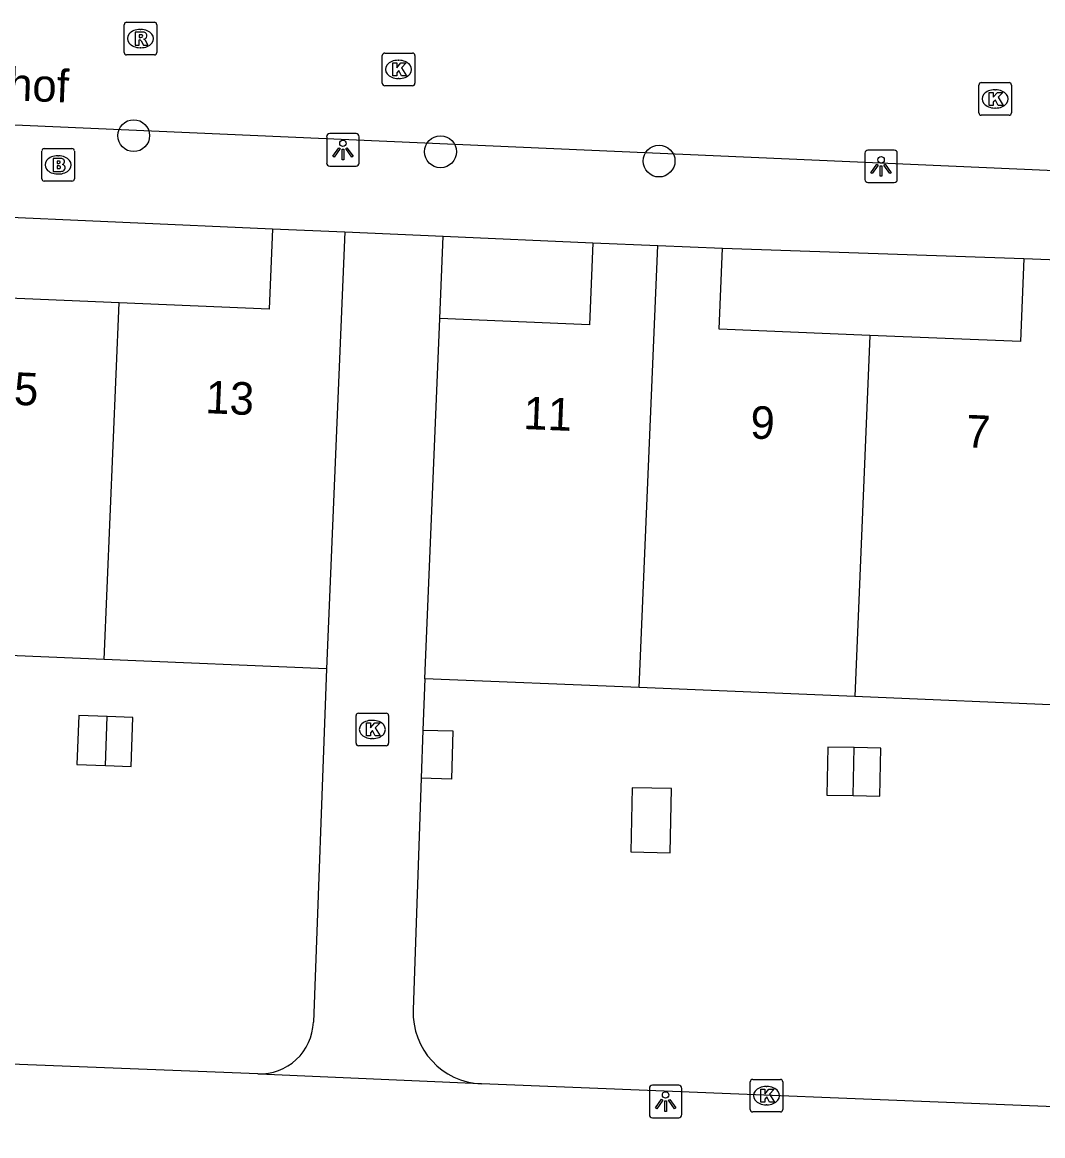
# Model space of a CAD drawing. Extents: x 160787 to 161428, y 386828 to 387483.
# Drawn here: x 161234.85 to 161266.19, y 386955.43 to 386989.61 of the extents above; entities that cross this region are included whole.
import ezdxf

# ---------------------------------------------------------------- set-up
doc = ezdxf.new("R2010")
doc.units = 0
for name, color, linetype in [('IMGEO_Boom', 7, 'Continuous'), ('IMGEO_Brandkraan', 7, 'Continuous'), ('IMGEO_Kolk', 7, 'Continuous'), ('IMGEO_Lichtpunt', 7, 'Continuous'), ('IMGEO_Openbare_ruimte_label', 7, 'Continuous'), ('IMGEO_Pand', 7, 'Continuous'), ('IMGEO_Pand_nummerreeks', 7, 'Continuous'), ('IMGEO_Parkeervlak_open', 7, 'Continuous'), ('IMGEO_Rijbaan_lokaal_open', 7, 'Continuous'), ('IMGEO_Rioolput', 7, 'Continuous'), ('IMGEO_Voetpad_open', 7, 'Continuous')]:
    doc.layers.add(name, color=color, linetype=linetype)

msp = doc.modelspace()

# ---------------------------------------------------------------- linework, layer by layer
at = {"layer": 'IMGEO_Boom'}
for centre in [(161238.273, 386986.13), (161247.693, 386985.636), (161254.405, 386985.35)]:
    msp.add_circle(centre, 0.489, dxfattribs=at)
at = {"layer": 'IMGEO_Brandkraan'}
for p, q in [((161235.45, 386984.807), (161235.45, 386985.659)), ((161235.525, 386985.733), (161236.377, 386985.733)), ((161236.451, 386985.659), (161236.451, 386984.807)), ((161235.938, 386985.513), (161235.963, 386985.513)), ((161235.961, 386984.953), (161235.936, 386984.953)), ((161236.377, 386984.733), (161235.525, 386984.733))]:
    msp.add_line(p, q, dxfattribs=at)
for points in [[(161235.45, 386984.807), (161235.45, 386985.659)], [(161235.525, 386985.733), (161236.377, 386985.733)], [(161236.451, 386985.659), (161236.451, 386984.807)], [(161235.798, 386985.433), (161235.798, 386985.033), (161236.011, 386985.033)], [(161236.029, 386985.433), (161235.798, 386985.433)], [(161235.977, 386985.352), (161235.923, 386985.352), (161235.923, 386985.276)], [(161235.923, 386985.276), (161235.976, 386985.276)], [(161235.985, 386985.2), (161235.923, 386985.2), (161235.923, 386985.119)], [(161235.923, 386985.119), (161235.985, 386985.119)], [(161236.377, 386984.733), (161235.525, 386984.733)]]:
    msp.add_lwpolyline(points, dxfattribs=at)
for centre, radius, start, end in [((161235.527, 386985.657), 0.0765, 91.552, 178.448), ((161235.527, 386985.657), 0.0765, 91.552, 178.448), ((161236.375, 386985.657), 0.0765, 1.552, 88.448), ((161236.375, 386985.657), 0.0765, 1.552, 88.448), ((161235.978, 386985.314), 0.0379, 267.8285, 90.9355), ((161236.033, 386985.288), 0.145, 59.4692, 91.5367), ((161236.058, 386985.335), 0.0922, 285.5137, 58.1501), ((161236.063, 386985.143), 0.105, 301.3115, 78.989), ((161235.986, 386985.159), 0.0404, 269.8759, 90.5077), ((161236.017, 386985.284), 0.251, 268.6676, 293.5347), ((161235.527, 386984.809), 0.0765, 181.552, 268.448), ((161235.527, 386984.809), 0.0765, 181.552, 268.448), ((161236.375, 386984.809), 0.0765, 271.552, 358.448), ((161236.375, 386984.809), 0.0765, 271.552, 358.448)]:
    msp.add_arc(centre, radius, start, end, dxfattribs=at)
for centre, major_axis, ratio, start_param, end_param in [((161235.937, 386985.233), (-0.387, 0.002), 0.722429, 4.712389, 7.853982), ((161235.962, 386985.233), (-0.39, 0.002), 0.717154, 1.570796, 4.712389)]:
    msp.add_ellipse(centre, major_axis=major_axis, ratio=ratio, start_param=start_param, end_param=end_param, dxfattribs=at)
at = {"layer": 'IMGEO_Kolk'}
for p, q in [((161245.98, 386988.663), (161246.832, 386988.663)), ((161245.905, 386987.737), (161245.905, 386988.589)), ((161246.393, 386988.443), (161246.418, 386988.443)), ((161246.906, 386988.589), (161246.906, 386987.737)), ((161246.832, 386987.663), (161245.98, 386987.663)), ((161246.416, 386987.883), (161246.391, 386987.883)), ((161264.225, 386986.832), (161264.225, 386987.684)), ((161264.3, 386987.758), (161265.152, 386987.758)), ((161265.226, 386987.684), (161265.226, 386986.832)), ((161264.713, 386987.538), (161264.738, 386987.538)), ((161264.736, 386986.978), (161264.711, 386986.978)), ((161265.152, 386986.758), (161264.3, 386986.758)), ((161245.099, 386967.477), (161245.099, 386968.329)), ((161245.174, 386968.403), (161246.026, 386968.403)), ((161245.587, 386968.183), (161245.612, 386968.183)), ((161246.1, 386968.329), (161246.1, 386967.477)), ((161245.61, 386967.623), (161245.585, 386967.623)), ((161246.026, 386967.403), (161245.174, 386967.403)), ((161257.205, 386956.236), (161257.205, 386957.088)), ((161257.28, 386957.162), (161258.132, 386957.162)), ((161257.693, 386956.942), (161257.718, 386956.942)), ((161258.206, 386957.088), (161258.206, 386956.236)), ((161257.716, 386956.382), (161257.691, 386956.382)), ((161258.132, 386956.162), (161257.28, 386956.162))]:
    msp.add_line(p, q, dxfattribs=at)
for points in [[(161245.98, 386988.663), (161246.832, 386988.663)], [(161245.905, 386987.737), (161245.905, 386988.589)], [(161246.226, 386988.363), (161246.349, 386988.363), (161246.349, 386988.212), (161246.479, 386988.363), (161246.643, 386988.363), (161246.497, 386988.212), (161246.65, 386987.963), (161246.498, 386987.963), (161246.413, 386988.127), (161246.349, 386988.06), (161246.349, 386987.963), (161246.226, 386987.963), (161246.226, 386988.363)], [(161246.906, 386988.589), (161246.906, 386987.737)], [(161246.832, 386987.663), (161245.98, 386987.663)], [(161264.225, 386986.832), (161264.225, 386987.684)], [(161264.3, 386987.758), (161265.152, 386987.758)], [(161265.226, 386987.684), (161265.226, 386986.832)], [(161264.546, 386987.458), (161264.669, 386987.458), (161264.669, 386987.307), (161264.799, 386987.458), (161264.963, 386987.458), (161264.817, 386987.307), (161264.97, 386987.058), (161264.818, 386987.058), (161264.733, 386987.222), (161264.669, 386987.155), (161264.669, 386987.058), (161264.546, 386987.058), (161264.546, 386987.458)], [(161265.152, 386986.758), (161264.3, 386986.758)], [(161245.099, 386967.477), (161245.099, 386968.329)], [(161245.174, 386968.403), (161246.026, 386968.403)], [(161246.1, 386968.329), (161246.1, 386967.477)], [(161245.42, 386968.103), (161245.543, 386968.103), (161245.543, 386967.952), (161245.673, 386968.103), (161245.837, 386968.103), (161245.691, 386967.952), (161245.844, 386967.703), (161245.692, 386967.703), (161245.607, 386967.867), (161245.543, 386967.8), (161245.543, 386967.703), (161245.42, 386967.703), (161245.42, 386968.103)], [(161246.026, 386967.403), (161245.174, 386967.403)], [(161257.205, 386956.236), (161257.205, 386957.088)], [(161257.28, 386957.162), (161258.132, 386957.162)], [(161257.526, 386956.862), (161257.649, 386956.862), (161257.649, 386956.711), (161257.779, 386956.862), (161257.943, 386956.862), (161257.797, 386956.711), (161257.95, 386956.462), (161257.798, 386956.462), (161257.713, 386956.626), (161257.649, 386956.559), (161257.649, 386956.462), (161257.526, 386956.462), (161257.526, 386956.862)], [(161258.206, 386957.088), (161258.206, 386956.236)], [(161258.132, 386956.162), (161257.28, 386956.162)]]:
    msp.add_lwpolyline(points, dxfattribs=at)
for centre, start, end in [((161245.982, 386988.587), 91.552, 178.448), ((161245.982, 386988.587), 91.552, 178.448), ((161246.83, 386988.587), 1.552, 88.448), ((161246.83, 386988.587), 1.552, 88.448), ((161245.982, 386987.739), 181.552, 268.448), ((161245.982, 386987.739), 181.552, 268.448), ((161246.83, 386987.739), 271.552, 358.448), ((161246.83, 386987.739), 271.552, 358.448), ((161264.302, 386987.682), 91.552, 178.448), ((161264.302, 386987.682), 91.552, 178.448), ((161265.15, 386987.682), 1.552, 88.448), ((161265.15, 386987.682), 1.552, 88.448), ((161264.302, 386986.834), 181.552, 268.448), ((161264.302, 386986.834), 181.552, 268.448), ((161265.15, 386986.834), 271.552, 358.448), ((161265.15, 386986.834), 271.552, 358.448), ((161245.176, 386968.327), 91.552, 178.448), ((161245.176, 386968.327), 91.552, 178.448), ((161246.024, 386968.327), 1.552, 88.448), ((161246.024, 386968.327), 1.552, 88.448), ((161245.176, 386967.479), 181.552, 268.448), ((161245.176, 386967.479), 181.552, 268.448), ((161246.024, 386967.479), 271.552, 358.448), ((161246.024, 386967.479), 271.552, 358.448), ((161257.282, 386957.086), 91.552, 178.448), ((161257.282, 386957.086), 91.552, 178.448), ((161258.13, 386957.086), 1.552, 88.448), ((161258.13, 386957.086), 1.552, 88.448), ((161257.282, 386956.238), 181.552, 268.448), ((161257.282, 386956.238), 181.552, 268.448), ((161258.13, 386956.238), 271.552, 358.448), ((161258.13, 386956.238), 271.552, 358.448)]:
    msp.add_arc(centre, 0.0765, start, end, dxfattribs=at)
for centre, major_axis, ratio, start_param, end_param in [((161246.392, 386988.163), (-0.387, 0.002), 0.722429, 4.712389, 7.853982), ((161246.417, 386988.163), (-0.39, 0.002), 0.717154, 1.570796, 4.712389), ((161264.712, 386987.258), (-0.387, 0.002), 0.722429, 4.712389, 7.853982), ((161264.737, 386987.258), (-0.39, 0.002), 0.717154, 1.570796, 4.712389), ((161245.586, 386967.903), (-0.387, 0.002), 0.722429, 4.712389, 7.853982), ((161245.611, 386967.903), (-0.39, 0.002), 0.717154, 1.570796, 4.712389), ((161257.692, 386956.662), (-0.387, 0.002), 0.722429, 4.712389, 7.853982), ((161257.717, 386956.662), (-0.39, 0.002), 0.717154, 1.570796, 4.712389)]:
    msp.add_ellipse(centre, major_axis=major_axis, ratio=ratio, start_param=start_param, end_param=end_param, dxfattribs=at)
at = {"layer": 'IMGEO_Lichtpunt'}
for p, q in [((161244.198, 386986.097), (161244.198, 386985.29)), ((161244.198, 386986.097), (161244.198, 386985.29)), ((161245.1, 386986.192), (161244.292, 386986.192)), ((161245.1, 386986.192), (161244.292, 386986.192)), ((161245.194, 386985.29), (161245.194, 386986.097)), ((161245.194, 386985.29), (161245.194, 386986.097)), ((161260.723, 386985.592), (161260.723, 386984.785)), ((161260.723, 386985.592), (161260.723, 386984.785)), ((161261.625, 386985.687), (161260.817, 386985.687)), ((161261.625, 386985.687), (161260.817, 386985.687)), ((161261.719, 386984.785), (161261.719, 386985.592)), ((161261.719, 386984.785), (161261.719, 386985.592)), ((161244.292, 386985.196), (161245.1, 386985.196)), ((161244.292, 386985.196), (161245.1, 386985.196)), ((161260.817, 386984.691), (161261.625, 386984.691)), ((161260.817, 386984.691), (161261.625, 386984.691)), ((161254.107, 386956.886), (161254.107, 386956.079)), ((161254.107, 386956.886), (161254.107, 386956.079)), ((161255.009, 386956.981), (161254.201, 386956.981)), ((161255.009, 386956.981), (161254.201, 386956.981)), ((161255.103, 386956.079), (161255.103, 386956.886)), ((161255.103, 386956.079), (161255.103, 386956.886)), ((161254.201, 386955.985), (161255.009, 386955.985)), ((161254.201, 386955.985), (161255.009, 386955.985))]:
    msp.add_line(p, q, dxfattribs=at)
for points in [[(161244.572, 386985.761), (161244.611, 386985.733), (161244.423, 386985.471), (161244.385, 386985.498), (161244.572, 386985.761)], [(161244.674, 386985.713), (161244.721, 386985.713), (161244.721, 386985.391), (161244.674, 386985.391), (161244.674, 386985.713)], [(161244.784, 386985.733), (161244.822, 386985.76), (161245.009, 386985.498), (161244.97, 386985.47), (161244.784, 386985.733)], [(161261.097, 386985.256), (161261.136, 386985.228), (161260.948, 386984.966), (161260.91, 386984.993), (161261.097, 386985.256)], [(161261.309, 386985.228), (161261.347, 386985.255), (161261.534, 386984.993), (161261.495, 386984.965), (161261.309, 386985.228)], [(161261.199, 386985.208), (161261.246, 386985.208), (161261.246, 386984.886), (161261.199, 386984.886), (161261.199, 386985.208)], [(161254.481, 386956.55), (161254.52, 386956.522), (161254.332, 386956.26), (161254.294, 386956.287), (161254.481, 386956.55)], [(161254.693, 386956.522), (161254.731, 386956.549), (161254.918, 386956.287), (161254.879, 386956.259), (161254.693, 386956.522)], [(161254.583, 386956.502), (161254.63, 386956.502), (161254.63, 386956.18), (161254.583, 386956.18), (161254.583, 386956.502)]]:
    msp.add_lwpolyline(points, dxfattribs=at)
for centre in [(161244.697, 386985.895), (161261.222, 386985.39), (161254.606, 386956.684)]:
    msp.add_circle(centre, 0.0994, dxfattribs=at)
for centre, start, end in [((161244.292, 386986.097), 90, 180), ((161244.292, 386986.097), 90, 180), ((161245.1, 386986.097), 0, 90), ((161245.1, 386986.097), 0, 90), ((161260.817, 386985.592), 90, 180), ((161260.817, 386985.592), 90, 180), ((161261.625, 386985.592), 0, 90), ((161261.625, 386985.592), 0, 90), ((161244.292, 386985.29), 180, 270), ((161244.292, 386985.29), 180, 270), ((161245.1, 386985.29), 270, 0), ((161245.1, 386985.29), 270, 360), ((161260.817, 386984.785), 180, 270), ((161260.817, 386984.785), 180, 270), ((161261.625, 386984.785), 270, 0), ((161261.625, 386984.785), 270, 360), ((161254.201, 386956.886), 90, 180), ((161254.201, 386956.886), 90, 180), ((161255.009, 386956.886), 0, 90), ((161255.009, 386956.886), 0, 90), ((161254.201, 386956.079), 180, 270), ((161254.201, 386956.079), 180, 270), ((161255.009, 386956.079), 270, 0), ((161255.009, 386956.079), 270, 360)]:
    msp.add_arc(centre, 0.0946, start, end, dxfattribs=at)
at = {"layer": 'IMGEO_Pand'}
for points in [[(161237.83, 386981), (161233.229, 386981.194), (161233.333, 386983.68)], [(161242.531, 386983.267), (161242.428, 386980.807), (161237.83, 386981)], [(161242.531, 386983.267), (161244.753, 386983.174)], [(161244.753, 386983.174), (161244.188, 386969.759)], [(161252.37, 386982.839), (161252.265, 386980.324), (161247.671, 386980.516)], [(161252.37, 386982.839), (161254.362, 386982.756)], [(161253.797, 386969.187), (161254.362, 386982.756)], [(161254.362, 386982.756), (161256.356, 386982.673)], [(161260.878, 386979.999), (161256.253, 386980.192), (161256.356, 386982.673)], [(161265.606, 386982.361), (161265.499, 386979.807), (161260.878, 386979.999)], [(161265.606, 386982.361), (161267.708, 386982.273)], [(161237.37, 386970.046), (161237.83, 386981)], [(161247.21, 386969.461), (161247.671, 386980.516)], [(161260.878, 386979.999), (161260.416, 386968.911)], [(161237.37, 386970.046), (161230.793, 386970.323)], [(161244.188, 386969.759), (161237.37, 386970.046)], [(161253.797, 386969.187), (161247.21, 386969.461)], [(161260.416, 386968.911), (161253.797, 386969.187)], [(161267.14, 386968.631), (161260.416, 386968.911)], [(161237.457, 386968.298), (161236.583, 386968.33), (161236.528, 386966.83), (161237.402, 386966.798)], [(161237.402, 386966.798), (161237.457, 386968.298)], [(161237.402, 386966.798), (161238.191, 386966.769), (161238.246, 386968.269), (161237.457, 386968.298)], [(161247.155, 386967.883), (161248.068, 386967.857), (161248.026, 386966.381), (161247.103, 386966.406)], [(161247.155, 386967.883), (161247.103, 386966.406)], [(161260.401, 386967.345), (161259.591, 386967.362), (161259.559, 386965.89), (161260.37, 386965.872)], [(161260.37, 386965.872), (161260.401, 386967.345)], [(161260.37, 386965.872), (161261.181, 386965.855), (161261.213, 386967.327), (161260.401, 386967.345)], [(161253.542, 386964.142), (161254.744, 386964.118), (161254.784, 386966.09), (161253.582, 386966.114), (161253.542, 386964.142)]]:
    msp.add_lwpolyline(points, dxfattribs=at)
at = {"layer": 'IMGEO_Parkeervlak_open'}
for points in [[(161233.333, 386983.68), (161242.531, 386983.267)], [(161247.777, 386983.048), (161252.37, 386982.839)], [(161256.356, 386982.673), (161265.606, 386982.361)]]:
    msp.add_lwpolyline(points, dxfattribs=at)
at = {"layer": 'IMGEO_Rijbaan_lokaal_open'}
msp.add_lwpolyline([(161291.727, 386983.944), (161185.206, 386988.619)], dxfattribs=at)
at = {"layer": 'IMGEO_Rioolput'}
for p, q in [((161237.98, 386988.684), (161237.98, 386989.536)), ((161238.055, 386989.61), (161238.907, 386989.61)), ((161238.468, 386989.39), (161238.493, 386989.39)), ((161238.981, 386989.536), (161238.981, 386988.684)), ((161238.491, 386988.83), (161238.466, 386988.83)), ((161238.907, 386988.61), (161238.055, 386988.61))]:
    msp.add_line(p, q, dxfattribs=at)
for points in [[(161237.98, 386988.684), (161237.98, 386989.536)], [(161238.055, 386989.61), (161238.907, 386989.61)], [(161238.981, 386989.536), (161238.981, 386988.684)], [(161238.569, 386989.308), (161238.317, 386989.31), (161238.317, 386988.91)], [(161238.317, 386988.91), (161238.441, 386988.91), (161238.441, 386989.072), (161238.452, 386989.072)], [(161238.495, 386989.229), (161238.441, 386989.229), (161238.441, 386989.148)], [(161238.441, 386989.148), (161238.493, 386989.148)], [(161238.499, 386989.043), (161238.57, 386988.91), (161238.71, 386988.91), (161238.645, 386989.036)], [(161238.907, 386988.61), (161238.055, 386988.61)]]:
    msp.add_lwpolyline(points, dxfattribs=at)
for centre, radius, start, end in [((161238.057, 386989.534), 0.0765, 91.552, 178.448), ((161238.057, 386989.534), 0.0765, 91.552, 178.448), ((161238.905, 386989.534), 0.0765, 1.552, 88.448), ((161238.905, 386989.534), 0.0765, 1.552, 88.448), ((161238.451, 386989.019), 0.0533, 26.0293, 88.6989), ((161238.477, 386989.337), 0.19, 274.7715, 282.9687), ((161238.501, 386989.133), 0.0964, 77.0061, 93.1865), ((161238.515, 386989.19), 0.0378, 276.6634, 79.6772), ((161238.568, 386989.198), 0.109, 350.3612, 89.416), ((161238.566, 386989.198), 0.112, 277.5842, 350.9817), ((161238.55, 386988.983), 0.108, 29.5134, 73.7905), ((161238.057, 386988.686), 0.0765, 181.552, 268.448), ((161238.057, 386988.686), 0.0765, 181.552, 268.448), ((161238.905, 386988.686), 0.0765, 271.552, 358.448), ((161238.905, 386988.686), 0.0765, 271.552, 358.448)]:
    msp.add_arc(centre, radius, start, end, dxfattribs=at)
for centre, major_axis, ratio, start_param, end_param in [((161238.467, 386989.11), (-0.387, 0.002), 0.722429, 4.712389, 7.853982), ((161238.492, 386989.11), (-0.39, 0.002), 0.717154, 1.570796, 4.712389)]:
    msp.add_ellipse(centre, major_axis=major_axis, ratio=ratio, start_param=start_param, end_param=end_param, dxfattribs=at)
at = {"layer": 'IMGEO_Voetpad_open'}
for points in [[(161244.753, 386983.174), (161247.777, 386983.048)], [(161247.671, 386980.516), (161247.777, 386983.048)], [(161244.188, 386969.759), (161243.789, 386958.916)], [(161247.21, 386969.461), (161247.155, 386967.883)], [(161247.103, 386966.406), (161246.854, 386959.292)], [(161242.084, 386957.33), (161186.392, 386959.511)], [(161248.948, 386957.027), (161248.924, 386957.025), (161242.12, 386957.323), (161242.084, 386957.33)], [(161288.733, 386955.432), (161248.948, 386957.027)]]:
    msp.add_lwpolyline(points, dxfattribs=at)
for centre, radius, start, end in [((161249.039, 386959.212), 2.187, 177.9021, 267.6049), ((161242.147, 386958.972), 1.643, 267.816, 358.0423)]:
    msp.add_arc(centre, radius, start, end, dxfattribs=at)

# ---------------------------------------------------------------- texts
at = {"layer": 'IMGEO_Openbare_ruimte_label'}
msp.add_text('Lenningenhof', height=1, rotation=357.7644, dxfattribs=at).set_placement((161228.161, 386987.462))
at = {"layer": 'IMGEO_Pand_nummerreeks'}
for s, rotation, p in [('15', 357.4941, (161233.838, 386977.904)), ('13', 357.4941, (161240.46, 386977.614)), ('11', 357.6246, (161250.225, 386977.127)), ('9', 357.6246, (161257.193, 386976.838)), ('7', 357.6246, (161263.814, 386976.564))]:
    msp.add_text(s, height=1, rotation=rotation, dxfattribs=at).set_placement(p)

doc.saveas('drawing.dxf')
